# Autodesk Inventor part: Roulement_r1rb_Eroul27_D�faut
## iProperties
Created: 2011-01
Part Number: Roulement_r1rb_Eroul27_D�faut
Document SubType Name: Modeling
Designer: eric
Density: 1 g/cm^3
Mass: 0.0579058 g
Surface Area: 0.723823 cm^2
Volume: 0.0579058 cm^3
Author: eric
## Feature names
1. Base1
